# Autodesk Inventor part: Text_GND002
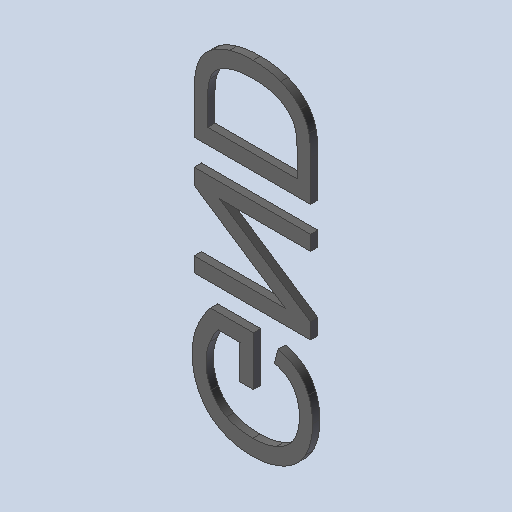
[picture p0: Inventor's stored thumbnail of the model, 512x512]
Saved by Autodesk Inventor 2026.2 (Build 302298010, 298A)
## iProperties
Created: 2026-10
Part Number: Text_GND002
Material: Générique
Document SubType Name: Modeling
Designer: mel
Density: 1 g/cm^3
Appearance: Par défaut
Author: mel
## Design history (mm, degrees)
feature "Base1"
feature "Base2"
feature "Base3"
node "Solide1"
node "Solide2"
node "Solide3"
